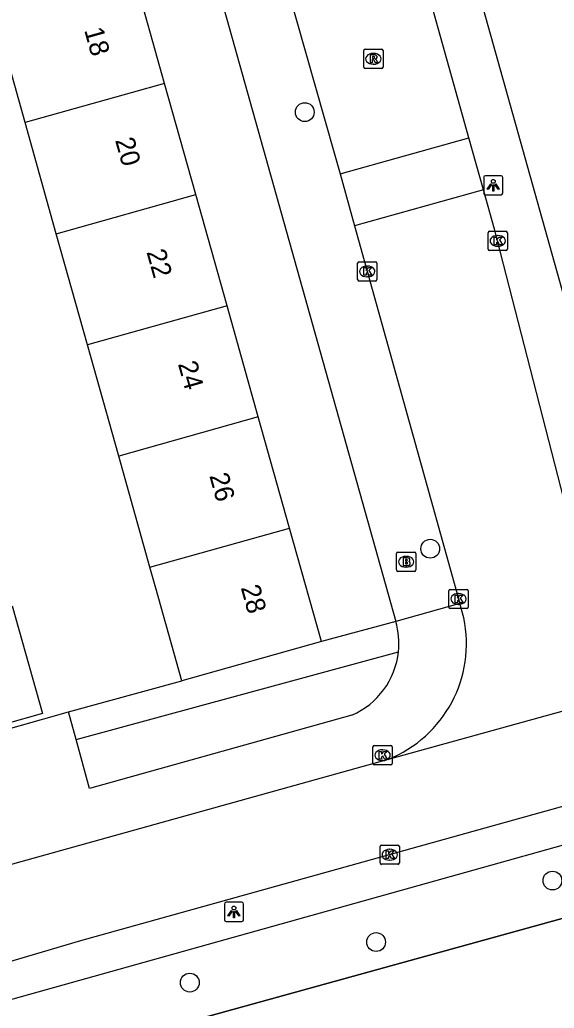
# Model space of a CAD drawing. Extents: x 159053 to 160041, y 380450 to 381422.
# Drawn here: x 159209.7 to 159237.4, y 380913.3 to 380964.7 of the extents above; entities that cross this region are included whole.
import ezdxf

# ---------------------------------------------------------------- set-up
doc = ezdxf.new("R2010")
doc.units = 0
for name, color, linetype in [('IMGEO_Boom', 7, 'Continuous'), ('IMGEO_Brandkraan', 7, 'Continuous'), ('IMGEO_Groenvoorziening', 7, 'Continuous'), ('IMGEO_Hek', 7, 'Continuous'), ('IMGEO_Kolk', 7, 'Continuous'), ('IMGEO_Lichtpunt', 7, 'Continuous'), ('IMGEO_Pand', 7, 'Continuous'), ('IMGEO_Pand_nummerreeks', 7, 'Continuous'), ('IMGEO_Rijbaan_lokaal_open', 7, 'Continuous'), ('IMGEO_Rioolput', 7, 'Continuous'), ('IMGEO_Voetpad_open', 7, 'Continuous')]:
    doc.layers.add(name, color=color, linetype=linetype)

msp = doc.modelspace()

# ---------------------------------------------------------------- linework, layer by layer
at = {"layer": 'IMGEO_Boom'}
for centre in [(159224.483, 380959.896), (159231.002, 380937.204), (159237.351, 380919.957), (159228.189, 380916.762), (159218.51, 380914.655)]:
    msp.add_circle(centre, 0.489, dxfattribs=at)
at = {"layer": 'IMGEO_Brandkraan'}
for p, q in [((159229.25, 380936.101), (159229.25, 380936.953)), ((159229.325, 380937.027), (159230.177, 380937.027)), ((159229.738, 380936.807), (159229.763, 380936.807)), ((159230.251, 380936.953), (159230.251, 380936.101)), ((159230.177, 380936.027), (159229.325, 380936.027)), ((159229.761, 380936.247), (159229.736, 380936.247))]:
    msp.add_line(p, q, dxfattribs=at)
for points in [[(159229.25, 380936.101), (159229.25, 380936.953)], [(159229.325, 380937.027), (159230.177, 380937.027)], [(159230.251, 380936.953), (159230.251, 380936.101)], [(159229.598, 380936.727), (159229.598, 380936.327), (159229.811, 380936.327)], [(159229.829, 380936.727), (159229.598, 380936.727)], [(159229.777, 380936.646), (159229.723, 380936.646), (159229.723, 380936.57)], [(159229.723, 380936.57), (159229.776, 380936.57)], [(159229.785, 380936.494), (159229.723, 380936.494), (159229.723, 380936.413)], [(159229.723, 380936.413), (159229.785, 380936.413)], [(159230.177, 380936.027), (159229.325, 380936.027)]]:
    msp.add_lwpolyline(points, dxfattribs=at)
for centre, radius, start, end in [((159229.327, 380936.951), 0.0765, 91.552, 178.448), ((159229.327, 380936.951), 0.0765, 91.552, 178.448), ((159230.175, 380936.951), 0.0765, 1.552, 88.448), ((159230.175, 380936.951), 0.0765, 1.552, 88.448), ((159229.778, 380936.608), 0.0379, 267.8285, 90.9355), ((159229.786, 380936.453), 0.0404, 269.8759, 90.5077), ((159229.817, 380936.578), 0.251, 268.6676, 293.5347), ((159229.833, 380936.582), 0.145, 59.4692, 91.5367), ((159229.858, 380936.629), 0.0922, 285.5137, 58.1501), ((159229.863, 380936.437), 0.105, 301.3115, 78.989), ((159229.327, 380936.103), 0.0765, 181.552, 268.448), ((159229.327, 380936.103), 0.0765, 181.552, 268.448), ((159230.175, 380936.103), 0.0765, 271.552, 358.448), ((159230.175, 380936.103), 0.0765, 271.552, 358.448)]:
    msp.add_arc(centre, radius, start, end, dxfattribs=at)
for centre, major_axis, ratio, start_param, end_param in [((159229.737, 380936.527), (-0.387, 0.002), 0.722429, 4.712389, 7.853982), ((159229.762, 380936.527), (-0.39, 0.002), 0.717154, 1.570796, 4.712389)]:
    msp.add_ellipse(centre, major_axis=major_axis, ratio=ratio, start_param=start_param, end_param=end_param, dxfattribs=at)
at = {"layer": 'IMGEO_Groenvoorziening'}
for points in [[(159296.42, 380934.314), (159296.448, 380934.184), (159194.979, 380906.143)], [(159229.211, 380933.416), (159225.347, 380932.375)], [(159212.602, 380927.289), (159229.352, 380931.854)], [(159212.208, 380928.733), (159218.1, 380930.34)]]:
    msp.add_lwpolyline(points, dxfattribs=at)
at = {"layer": 'IMGEO_Hek'}
msp.add_lwpolyline([(159194.979, 380906.143), (159296.448, 380934.184)], dxfattribs=at)
at = {"layer": 'IMGEO_Kolk'}
for p, q in [((159234.009, 380952.776), (159234.009, 380953.628)), ((159234.084, 380953.702), (159234.936, 380953.702)), ((159234.497, 380953.482), (159234.522, 380953.482)), ((159235.01, 380953.628), (159235.01, 380952.776)), ((159234.52, 380952.922), (159234.495, 380952.922)), ((159234.936, 380952.702), (159234.084, 380952.702)), ((159227.226, 380951.191), (159227.226, 380952.043)), ((159227.301, 380952.117), (159228.153, 380952.117)), ((159227.714, 380951.897), (159227.739, 380951.897)), ((159228.227, 380952.043), (159228.227, 380951.191)), ((159227.737, 380951.337), (159227.712, 380951.337)), ((159228.153, 380951.117), (159227.301, 380951.117)), ((159231.97, 380934.167), (159231.97, 380935.019)), ((159232.045, 380935.093), (159232.897, 380935.093)), ((159232.458, 380934.873), (159232.483, 380934.873)), ((159232.971, 380935.019), (159232.971, 380934.167)), ((159232.481, 380934.313), (159232.456, 380934.313)), ((159232.897, 380934.093), (159232.045, 380934.093)), ((159228.024, 380926.048), (159228.024, 380926.9)), ((159228.099, 380926.974), (159228.951, 380926.974)), ((159228.512, 380926.754), (159228.537, 380926.754)), ((159229.025, 380926.9), (159229.025, 380926.048)), ((159228.535, 380926.194), (159228.51, 380926.194)), ((159228.951, 380925.974), (159228.099, 380925.974)), ((159228.396, 380920.876), (159228.396, 380921.728)), ((159228.471, 380921.802), (159229.323, 380921.802)), ((159228.884, 380921.582), (159228.909, 380921.582)), ((159229.397, 380921.728), (159229.397, 380920.876)), ((159228.907, 380921.022), (159228.882, 380921.022)), ((159229.323, 380920.802), (159228.471, 380920.802))]:
    msp.add_line(p, q, dxfattribs=at)
for points in [[(159234.009, 380952.776), (159234.009, 380953.628)], [(159234.084, 380953.702), (159234.936, 380953.702)], [(159234.33, 380953.402), (159234.453, 380953.402), (159234.453, 380953.251), (159234.583, 380953.402), (159234.747, 380953.402), (159234.601, 380953.251), (159234.754, 380953.002), (159234.602, 380953.002), (159234.517, 380953.166), (159234.453, 380953.099), (159234.453, 380953.002), (159234.33, 380953.002), (159234.33, 380953.402)], [(159235.01, 380953.628), (159235.01, 380952.776)], [(159234.936, 380952.702), (159234.084, 380952.702)], [(159227.226, 380951.191), (159227.226, 380952.043)], [(159227.301, 380952.117), (159228.153, 380952.117)], [(159227.547, 380951.817), (159227.67, 380951.817), (159227.67, 380951.666), (159227.8, 380951.817), (159227.964, 380951.817), (159227.818, 380951.666), (159227.971, 380951.417), (159227.819, 380951.417), (159227.734, 380951.581), (159227.67, 380951.514), (159227.67, 380951.417), (159227.547, 380951.417), (159227.547, 380951.817)], [(159228.227, 380952.043), (159228.227, 380951.191)], [(159228.153, 380951.117), (159227.301, 380951.117)], [(159231.97, 380934.167), (159231.97, 380935.019)], [(159232.045, 380935.093), (159232.897, 380935.093)], [(159232.291, 380934.793), (159232.414, 380934.793), (159232.414, 380934.642), (159232.544, 380934.793), (159232.708, 380934.793), (159232.562, 380934.642), (159232.715, 380934.393), (159232.563, 380934.393), (159232.478, 380934.557), (159232.414, 380934.49), (159232.414, 380934.393), (159232.291, 380934.393), (159232.291, 380934.793)], [(159232.971, 380935.019), (159232.971, 380934.167)], [(159232.897, 380934.093), (159232.045, 380934.093)], [(159228.024, 380926.048), (159228.024, 380926.9)], [(159228.099, 380926.974), (159228.951, 380926.974)], [(159228.345, 380926.674), (159228.468, 380926.674), (159228.468, 380926.523), (159228.598, 380926.674), (159228.762, 380926.674), (159228.616, 380926.523), (159228.769, 380926.274), (159228.617, 380926.274), (159228.532, 380926.438), (159228.468, 380926.371), (159228.468, 380926.274), (159228.345, 380926.274), (159228.345, 380926.674)], [(159229.025, 380926.9), (159229.025, 380926.048)], [(159228.951, 380925.974), (159228.099, 380925.974)], [(159228.396, 380920.876), (159228.396, 380921.728)], [(159228.471, 380921.802), (159229.323, 380921.802)], [(159228.717, 380921.502), (159228.84, 380921.502), (159228.84, 380921.351), (159228.97, 380921.502), (159229.134, 380921.502), (159228.988, 380921.351), (159229.141, 380921.102), (159228.989, 380921.102), (159228.904, 380921.266), (159228.84, 380921.199), (159228.84, 380921.102), (159228.717, 380921.102), (159228.717, 380921.502)], [(159229.397, 380921.728), (159229.397, 380920.876)], [(159229.323, 380920.802), (159228.471, 380920.802)]]:
    msp.add_lwpolyline(points, dxfattribs=at)
for centre, start, end in [((159234.086, 380953.626), 91.552, 178.448), ((159234.086, 380953.626), 91.552, 178.448), ((159234.934, 380953.626), 1.552, 88.448), ((159234.934, 380953.626), 1.552, 88.448), ((159234.086, 380952.778), 181.552, 268.448), ((159234.086, 380952.778), 181.552, 268.448), ((159234.934, 380952.778), 271.552, 358.448), ((159234.934, 380952.778), 271.552, 358.448), ((159227.303, 380952.041), 91.552, 178.448), ((159227.303, 380952.041), 91.552, 178.448), ((159228.151, 380952.041), 1.552, 88.448), ((159228.151, 380952.041), 1.552, 88.448), ((159227.303, 380951.193), 181.552, 268.448), ((159227.303, 380951.193), 181.552, 268.448), ((159228.151, 380951.193), 271.552, 358.448), ((159228.151, 380951.193), 271.552, 358.448), ((159232.047, 380935.017), 91.552, 178.448), ((159232.047, 380935.017), 91.552, 178.448), ((159232.895, 380935.017), 1.552, 88.448), ((159232.895, 380935.017), 1.552, 88.448), ((159232.047, 380934.169), 181.552, 268.448), ((159232.047, 380934.169), 181.552, 268.448), ((159232.895, 380934.169), 271.552, 358.448), ((159232.895, 380934.169), 271.552, 358.448), ((159228.101, 380926.898), 91.552, 178.448), ((159228.101, 380926.898), 91.552, 178.448), ((159228.949, 380926.898), 1.552, 88.448), ((159228.949, 380926.898), 1.552, 88.448), ((159228.101, 380926.05), 181.552, 268.448), ((159228.101, 380926.05), 181.552, 268.448), ((159228.949, 380926.05), 271.552, 358.448), ((159228.949, 380926.05), 271.552, 358.448), ((159228.473, 380921.726), 91.552, 178.448), ((159228.473, 380921.726), 91.552, 178.448), ((159229.321, 380921.726), 1.552, 88.448), ((159229.321, 380921.726), 1.552, 88.448), ((159228.473, 380920.878), 181.552, 268.448), ((159228.473, 380920.878), 181.552, 268.448), ((159229.321, 380920.878), 271.552, 358.448), ((159229.321, 380920.878), 271.552, 358.448)]:
    msp.add_arc(centre, 0.0765, start, end, dxfattribs=at)
for centre, major_axis, ratio, start_param, end_param in [((159234.496, 380953.202), (-0.387, 0.002), 0.722429, 4.712389, 7.853982), ((159234.521, 380953.202), (-0.39, 0.002), 0.717154, 1.570796, 4.712389), ((159227.713, 380951.617), (-0.387, 0.002), 0.722429, 4.712389, 7.853982), ((159227.738, 380951.617), (-0.39, 0.002), 0.717154, 1.570796, 4.712389), ((159232.457, 380934.593), (-0.387, 0.002), 0.722429, 4.712389, 7.853982), ((159232.482, 380934.593), (-0.39, 0.002), 0.717154, 1.570796, 4.712389), ((159228.511, 380926.474), (-0.387, 0.002), 0.722429, 4.712389, 7.853982), ((159228.536, 380926.474), (-0.39, 0.002), 0.717154, 1.570796, 4.712389), ((159228.883, 380921.302), (-0.387, 0.002), 0.722429, 4.712389, 7.853982), ((159228.908, 380921.302), (-0.39, 0.002), 0.717154, 1.570796, 4.712389)]:
    msp.add_ellipse(centre, major_axis=major_axis, ratio=ratio, start_param=start_param, end_param=end_param, dxfattribs=at)
at = {"layer": 'IMGEO_Lichtpunt'}
for p, q in [((159233.778, 380956.498), (159233.778, 380955.691)), ((159233.778, 380956.498), (159233.778, 380955.691)), ((159234.68, 380956.593), (159233.872, 380956.593)), ((159234.68, 380956.593), (159233.872, 380956.593)), ((159234.774, 380955.691), (159234.774, 380956.498)), ((159234.774, 380955.691), (159234.774, 380956.498)), ((159233.872, 380955.597), (159234.68, 380955.597)), ((159233.872, 380955.597), (159234.68, 380955.597)), ((159221.208, 380918.828), (159220.4, 380918.828)), ((159221.208, 380918.828), (159220.4, 380918.828)), ((159220.306, 380918.733), (159220.306, 380917.926)), ((159220.306, 380918.733), (159220.306, 380917.926)), ((159221.302, 380917.926), (159221.302, 380918.733)), ((159221.302, 380917.926), (159221.302, 380918.733)), ((159220.4, 380917.832), (159221.208, 380917.832)), ((159220.4, 380917.832), (159221.208, 380917.832))]:
    msp.add_line(p, q, dxfattribs=at)
for points in [[(159234.152, 380956.162), (159234.191, 380956.134), (159234.003, 380955.872), (159233.965, 380955.899), (159234.152, 380956.162)], [(159234.254, 380956.114), (159234.301, 380956.114), (159234.301, 380955.792), (159234.254, 380955.792), (159234.254, 380956.114)], [(159234.364, 380956.134), (159234.402, 380956.161), (159234.589, 380955.899), (159234.55, 380955.871), (159234.364, 380956.134)], [(159220.68, 380918.397), (159220.719, 380918.369), (159220.531, 380918.107), (159220.493, 380918.134), (159220.68, 380918.397)], [(159220.782, 380918.349), (159220.829, 380918.349), (159220.829, 380918.027), (159220.782, 380918.027), (159220.782, 380918.349)], [(159220.892, 380918.369), (159220.93, 380918.396), (159221.117, 380918.134), (159221.078, 380918.106), (159220.892, 380918.369)]]:
    msp.add_lwpolyline(points, dxfattribs=at)
for centre in [(159234.277, 380956.296), (159220.805, 380918.531)]:
    msp.add_circle(centre, 0.0994, dxfattribs=at)
for centre, start, end in [((159233.872, 380956.498), 90, 180), ((159233.872, 380956.498), 90, 180), ((159234.68, 380956.498), 0, 90), ((159234.68, 380956.498), 0, 90), ((159233.872, 380955.691), 180, 270), ((159233.872, 380955.691), 180, 270), ((159234.68, 380955.691), 270, 0), ((159234.68, 380955.691), 270, 360), ((159220.4, 380918.733), 90, 180), ((159220.4, 380918.733), 90, 180), ((159221.208, 380918.733), 0, 90), ((159221.208, 380918.733), 0, 90), ((159220.4, 380917.926), 180, 270), ((159220.4, 380917.926), 180, 270), ((159221.208, 380917.926), 270, 0), ((159221.208, 380917.926), 270, 360)]:
    msp.add_arc(centre, 0.0946, start, end, dxfattribs=at)
at = {"layer": 'IMGEO_Pand'}
for points in [[(159217.202, 380961.384), (159215.58, 380967.161)], [(159209.955, 380959.35), (159208.333, 380965.127)], [(159217.202, 380961.384), (159209.955, 380959.35)], [(159218.824, 380955.608), (159217.202, 380961.384)], [(159211.576, 380953.574), (159209.955, 380959.35)], [(159211.576, 380953.574), (159218.824, 380955.608)], [(159220.446, 380949.831), (159218.824, 380955.608)], [(159213.198, 380947.797), (159211.576, 380953.574)], [(159220.446, 380949.831), (159213.198, 380947.797)], [(159222.068, 380944.054), (159220.446, 380949.831)], [(159214.82, 380942.021), (159213.198, 380947.797)], [(159222.068, 380944.054), (159214.82, 380942.021)], [(159223.69, 380938.278), (159222.068, 380944.054)], [(159216.442, 380936.244), (159214.82, 380942.021)], [(159216.442, 380936.244), (159223.69, 380938.278)], [(159225.347, 380932.375), (159223.69, 380938.278)], [(159218.1, 380930.34), (159216.748, 380935.154), (159216.442, 380936.244)], [(159209.282, 380934.235), (159210.854, 380928.637), (159206.922, 380927.533), (159205.35, 380933.131)], [(159225.347, 380932.375), (159218.1, 380930.34)]]:
    msp.add_lwpolyline(points, dxfattribs=at)
at = {"layer": 'IMGEO_Rijbaan_lokaal_open'}
for points in [[(159233.01, 380958.559), (159227.69, 380977.591), (159222.598, 380995.644), (159221.437, 381000), (159221.152, 381001.023)], [(159214.376, 380999.135), (159215.914, 380993.702), (159219.592, 380980.397), (159226.01, 380957.779), (159226.315, 380956.684)], [(159226.315, 380956.684), (159233.01, 380958.559)], [(159233.764, 380955.863), (159233.01, 380958.559)], [(159226.315, 380956.684), (159227.067, 380953.987)], [(159233.764, 380955.863), (159227.067, 380953.987)], [(159238.874, 380936.156), (159234.335, 380953.821), (159233.764, 380955.863)], [(159227.067, 380953.987), (159231.034, 380939.757), (159232.538, 380934.356)], [(159232.744, 380933.615), (159232.538, 380934.356)], [(159270.392, 380932.872), (159251.048, 380927.477), (159212.83, 380916.824), (159205.315, 380914.615)], [(159245.785, 380930.949), (159228.811, 380926.254)], [(159228.811, 380926.254), (159204.121, 380919.367)]]:
    msp.add_lwpolyline(points, dxfattribs=at)
msp.add_arc((159226.392, 380932.278), 6.491, 291.8774, 11.8912, dxfattribs=at)
at = {"layer": 'IMGEO_Rioolput'}
for p, q in [((159227.547, 380962.241), (159227.547, 380963.093)), ((159227.622, 380963.167), (159228.474, 380963.167)), ((159228.548, 380963.093), (159228.548, 380962.241)), ((159228.035, 380962.947), (159228.06, 380962.947)), ((159228.474, 380962.167), (159227.622, 380962.167)), ((159228.058, 380962.387), (159228.033, 380962.387))]:
    msp.add_line(p, q, dxfattribs=at)
for points in [[(159227.547, 380962.241), (159227.547, 380963.093)], [(159227.622, 380963.167), (159228.474, 380963.167)], [(159228.548, 380963.093), (159228.548, 380962.241)], [(159228.136, 380962.865), (159227.884, 380962.867), (159227.884, 380962.467)], [(159227.884, 380962.467), (159228.008, 380962.467), (159228.008, 380962.629), (159228.019, 380962.629)], [(159228.062, 380962.786), (159228.008, 380962.786), (159228.008, 380962.705)], [(159228.008, 380962.705), (159228.06, 380962.705)], [(159228.066, 380962.6), (159228.137, 380962.467), (159228.277, 380962.467), (159228.212, 380962.593)], [(159228.474, 380962.167), (159227.622, 380962.167)]]:
    msp.add_lwpolyline(points, dxfattribs=at)
for centre, radius, start, end in [((159227.624, 380963.091), 0.0765, 91.552, 178.448), ((159227.624, 380963.091), 0.0765, 91.552, 178.448), ((159228.472, 380963.091), 0.0765, 1.552, 88.448), ((159228.472, 380963.091), 0.0765, 1.552, 88.448), ((159228.018, 380962.576), 0.0533, 26.0293, 88.6989), ((159228.044, 380962.894), 0.19, 274.7715, 282.9687), ((159228.068, 380962.69), 0.0964, 77.0061, 93.1865), ((159228.082, 380962.747), 0.0378, 276.6634, 79.6772), ((159228.135, 380962.755), 0.109, 350.3612, 89.416), ((159228.133, 380962.755), 0.112, 277.5842, 350.9817), ((159228.117, 380962.54), 0.108, 29.5134, 73.7905), ((159227.624, 380962.243), 0.0765, 181.552, 268.448), ((159227.624, 380962.243), 0.0765, 181.552, 268.448), ((159228.472, 380962.243), 0.0765, 271.552, 358.448), ((159228.472, 380962.243), 0.0765, 271.552, 358.448)]:
    msp.add_arc(centre, radius, start, end, dxfattribs=at)
for centre, major_axis, ratio, start_param, end_param in [((159228.034, 380962.667), (-0.387, 0.002), 0.722429, 4.712389, 7.853982), ((159228.059, 380962.667), (-0.39, 0.002), 0.717154, 1.570796, 4.712389)]:
    msp.add_ellipse(centre, major_axis=major_axis, ratio=ratio, start_param=start_param, end_param=end_param, dxfattribs=at)
at = {"layer": 'IMGEO_Voetpad_open'}
for points in [[(159241.698, 380936.943), (159224.043, 381000), (159217.284, 381024.142)], [(159204.751, 381020.689), (159210.55, 381000), (159229.211, 380933.416)], [(159194.248, 380908.271), (159195.395, 380909.913), (159199.726, 380911.13), (159295.42, 380937.918), (159296.393, 380934.435), (159296.42, 380934.314)], [(159232.538, 380934.356), (159229.211, 380933.416)], [(159207.189, 380927.306), (159212.208, 380928.733)], [(159212.602, 380927.289), (159212.208, 380928.733)], [(159226.936, 380928.562), (159213.294, 380924.749), (159212.602, 380927.289)]]:
    msp.add_lwpolyline(points, dxfattribs=at)
for centre, radius, start, end in [((159225.334, 380932.279), 4.041, 353.9681, 16.348), ((159225.327, 380932.275), 4.047, 293.4266, 354.0235)]:
    msp.add_arc(centre, radius, start, end, dxfattribs=at)

# ---------------------------------------------------------------- texts
at = {"layer": 'IMGEO_Pand_nummerreeks'}
for s, p in [('18', (159213.016, 380964.162)), ('20', (159214.623, 380958.438)), ('22', (159216.253, 380952.631)), ('24', (159217.886, 380946.816)), ('26', (159219.518, 380941.003)), ('28', (159221.151, 380935.187))]:
    msp.add_text(s, height=1, rotation=285.6832, dxfattribs=at).set_placement(p)

doc.saveas('drawing.dxf')
